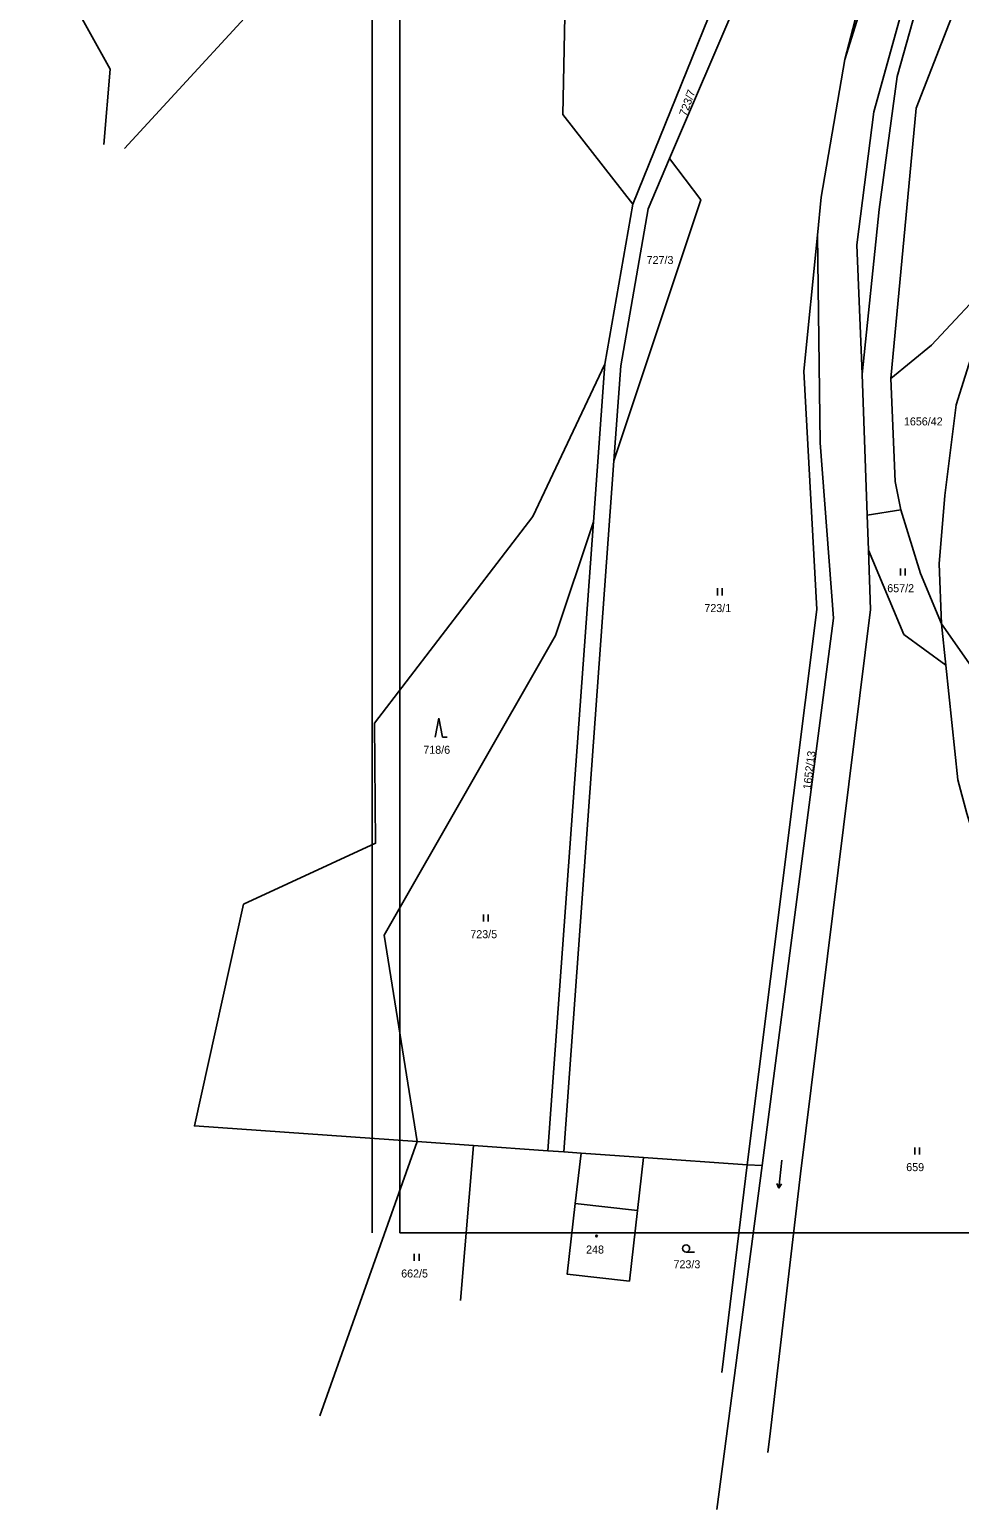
# Model space of a CAD drawing. Extents: x -553916 to -552953, y -1067470 to -1066637.
# Drawn here: x -553872.7 to -553675.3, y -1067469 to -1067154.7 of the extents above; entities that cross this region are included whole.
import ezdxf

# ---------------------------------------------------------------- set-up
doc = ezdxf.new("R2010")
doc.units = 0
for name, color, linetype in [('Hranice parcel', 7, 'Continuous'), ('Parcelní čísla', 7, 'Continuous'), ('Vnitřní kresba', 7, 'Continuous'), ('Vrstva 1', 7, 'Continuous'), ('Značky budov', 7, 'Continuous'), ('Značky kultur', 7, 'Continuous')]:
    doc.layers.add(name, color=color, linetype=linetype)

msp = doc.modelspace()

# ---------------------------------------------------------------- linework, layer by layer
at = {"layer": 'Hranice parcel'}
for p, q in [((-553682.64, -1067055.36), (-553736.85, -1067182.11)), ((-553699.64, -1067161.1), (-553692.26, -1067132.51)), ((-553744.69, -1067191.8), (-553750.62, -1067225.75)), ((-553750.62, -1067225.75), (-553753.04, -1067259.3)), ((-553695.94, -1067227.92), (-553694.89, -1067257.82)), ((-553748.69, -1067246.29), (-553759.3, -1067393.1)), ((-553694.89, -1067257.82), (-553687.76, -1067256.69)), ((-553762.69, -1067392.86), (-553753.04, -1067259.3)), ((-553694.89, -1067257.82), (-553694.63, -1067265.31)), ((-553678.21, -1067289.69), (-553679.12, -1067280.91)), ((-553675.68, -1067314.09), (-553678.21, -1067289.69)), ((-553790.46, -1067390.9), (-553811.08, -1067449.2)), ((-553790.46, -1067390.9), (-553778.49, -1067391.74)), ((-553778.49, -1067391.74), (-553781.25, -1067424.65)), ((-553762.69, -1067392.86), (-553778.49, -1067391.74)), ((-553759.3, -1067393.1), (-553762.69, -1067392.86)), ((-553759.3, -1067393.1), (-553755.65, -1067393.35)), ((-553742.38, -1067394.29), (-553755.65, -1067393.35)), ((-553742.38, -1067394.29), (-553720.38, -1067395.83)), ((-553717.22, -1067396.01), (-553726.82, -1067469.04)), ((-553725.77, -1067439.98), (-553720.38, -1067395.83)), ((-553720.38, -1067395.83), (-553717.22, -1067396.01))]:
    msp.add_line(p, q, dxfattribs=at)
for points in [[(-553648.57, -1066991.82), (-553659.32, -1067017.01), (-553678.4, -1067093.07), (-553699.64, -1067161.1)], [(-553695.94, -1067227.92), (-553697.09, -1067200.45), (-553693.46, -1067172.18), (-553652.47, -1067024.37)], [(-553856.98, -1067179.12), (-553855.63, -1067163.09), (-553864, -1067148.03), (-553860.02, -1067146.13), (-553872.73, -1067094.13), (-553844.72, -1067085.79), (-553834.37, -1067133.89), (-553804.82, -1067119.79), (-553771, -1067105.16), (-553739.65, -1067037.62)], [(-553655.53, -1067040.29), (-553660.05, -1067063.23), (-553688.55, -1067164.71), (-553692.38, -1067192.94), (-553695.94, -1067227.92)], [(-553691.88, -1067055.11), (-553698.79, -1067078.47), (-553744.69, -1067191.8)], [(-553648.45, -1067052.9), (-553657.29, -1067086.06), (-553666.21, -1067098.13), (-553670.52, -1067135.37), (-553684.51, -1067171.37), (-553689.91, -1067228.79)], [(-553852.6, -1067180), (-553815.54, -1067139.66), (-553779.26, -1067146.56), (-553772.79, -1067113.94), (-553753.66, -1067113.05), (-553758.92, -1067144.82), (-553759.49, -1067172.72), (-553744.69, -1067191.8)], [(-553705.47, -1067198.37), (-553704.66, -1067190.29), (-553699.64, -1067161.1)], [(-553748.69, -1067246.29), (-553747.24, -1067226.17), (-553741.4, -1067192.77), (-553736.85, -1067182.11)], [(-553736.85, -1067182.11), (-553730.23, -1067190.89), (-553748.69, -1067246.29)], [(-553689.91, -1067228.79), (-553681.28, -1067221.74), (-553667.99, -1067207.55), (-553660.17, -1067189.87)], [(-553660.17, -1067189.87), (-553665.44, -1067205.7), (-553670.26, -1067216.16), (-553675.98, -1067234.41), (-553678.44, -1067253.69), (-553679.63, -1067268.16), (-553679.12, -1067280.91)], [(-553720.38, -1067395.83), (-553705.59, -1067277.88), (-553708.38, -1067227.3), (-553705.47, -1067198.37)], [(-553717.22, -1067396.01), (-553702.06, -1067279.73), (-553704.85, -1067242.51), (-553705.47, -1067198.37)], [(-553750.62, -1067225.75), (-553765.92, -1067258.16), (-553799.48, -1067302.04), (-553799.26, -1067327.54), (-553827.3, -1067340.5), (-553837.73, -1067387.58), (-553790.46, -1067390.9)], [(-553687.76, -1067256.69), (-553688.96, -1067250.67), (-553689.91, -1067228.79)], [(-553679.12, -1067280.91), (-553683.6, -1067270.21), (-553687.76, -1067256.69)], [(-553753.04, -1067259.3), (-553761.11, -1067283.4), (-553797.47, -1067347.09), (-553790.46, -1067390.9)], [(-553694.63, -1067265.31), (-553694.19, -1067277.87), (-553709.03, -1067397.74), (-553715.41, -1067452.36), (-553716.03, -1067456.95)], [(-553694.63, -1067265.31), (-553687.13, -1067283.19), (-553678.21, -1067289.69)], [(-553679.12, -1067280.91), (-553661.1, -1067306.72), (-553656.17, -1067315.75)], [(-553654.47, -1067375.83), (-553662.26, -1067358.39), (-553673.71, -1067321.24), (-553675.68, -1067314.09)], [(-553755.65, -1067393.35), (-553756.88, -1067404.04), (-553758.6, -1067419.04), (-553745.39, -1067420.55), (-553743.67, -1067405.55), (-553742.38, -1067394.29)]]:
    msp.add_lwpolyline(points, dxfattribs=at)
at = {"layer": 'Vnitřní kresba'}
msp.add_line((-553756.88, -1067404.04), (-553743.67, -1067405.55), dxfattribs=at)
at = {"layer": 'Vrstva 1'}
for p, q in [((-553794.11, -1067410.27), (-553794.11, -1066816.27)), ((-552953.11, -1067410.27), (-553794.11, -1067410.27))]:
    msp.add_line(p, q, dxfattribs=at)
msp.add_lwpolyline([(-553800, -1067410.27), (-553800, -1067100), (-553300, -1067100), (-553300, -1067410.27)], dxfattribs=at)
at = {"layer": 'Značky budov'}
msp.add_circle((-553752.36, -1067410.97), 0.175, dxfattribs=at)
at = {"layer": 'Značky kultur'}
for p, q in [((-553687.85, -1067270.67), (-553687.85, -1067269.17)), ((-553686.85, -1067270.67), (-553686.85, -1067269.17)), ((-553726.68, -1067274.89), (-553726.68, -1067273.39)), ((-553725.68, -1067274.89), (-553725.68, -1067273.39)), ((-553785.84, -1067300.99), (-553786.59, -1067304.99)), ((-553785.09, -1067304.99), (-553785.84, -1067300.99)), ((-553785.09, -1067304.99), (-553784.09, -1067304.99)), ((-553776.37, -1067344.16), (-553776.37, -1067342.66)), ((-553775.37, -1067344.16), (-553775.37, -1067342.66)), ((-553713.04, -1067394.85), (-553713.66, -1067400.82)), ((-553684.8, -1067393.64), (-553684.8, -1067392.14)), ((-553683.8, -1067393.64), (-553683.8, -1067392.14)), ((-553713.66, -1067400.82), (-553714.06, -1067399.8)), ((-553713.66, -1067400.82), (-553713.06, -1067399.9)), ((-553791.05, -1067416.23), (-553791.05, -1067414.73)), ((-553790.05, -1067416.23), (-553790.05, -1067414.73)), ((-553733.35, -1067414.37), (-553731.6, -1067414.37))]:
    msp.add_line(p, q, dxfattribs=at)
msp.add_circle((-553733.35, -1067413.62), 0.75, dxfattribs=at)

# ---------------------------------------------------------------- texts
at = {"layer": 'Parcelní čísla'}
for s, rotation, p in [('723/7', 70, (-553733.29, -1067173.23)), ('1652/13', 83, (-553706.87, -1067316.2))]:
    msp.add_text(s, height=1.7, rotation=rotation, dxfattribs=at).set_placement(p)
for s, p in [('727/3', (-553741.73, -1067204.5)), ('1656/42', (-553687.1, -1067238.79)), ('657/2', (-553690.64, -1067274.22)), ('723/1', (-553729.47, -1067278.44)), ('718/6', (-553789.14, -1067308.54)), ('723/5', (-553779.16, -1067347.71)), ('659', (-553686.61, -1067397.19)), ('248', (-553754.58, -1067414.69)), ('723/3', (-553736.02, -1067417.82)), ('662/5', (-553793.84, -1067419.78))]:
    msp.add_text(s, height=1.7, dxfattribs=at).set_placement(p)

doc.saveas('drawing.dxf')
